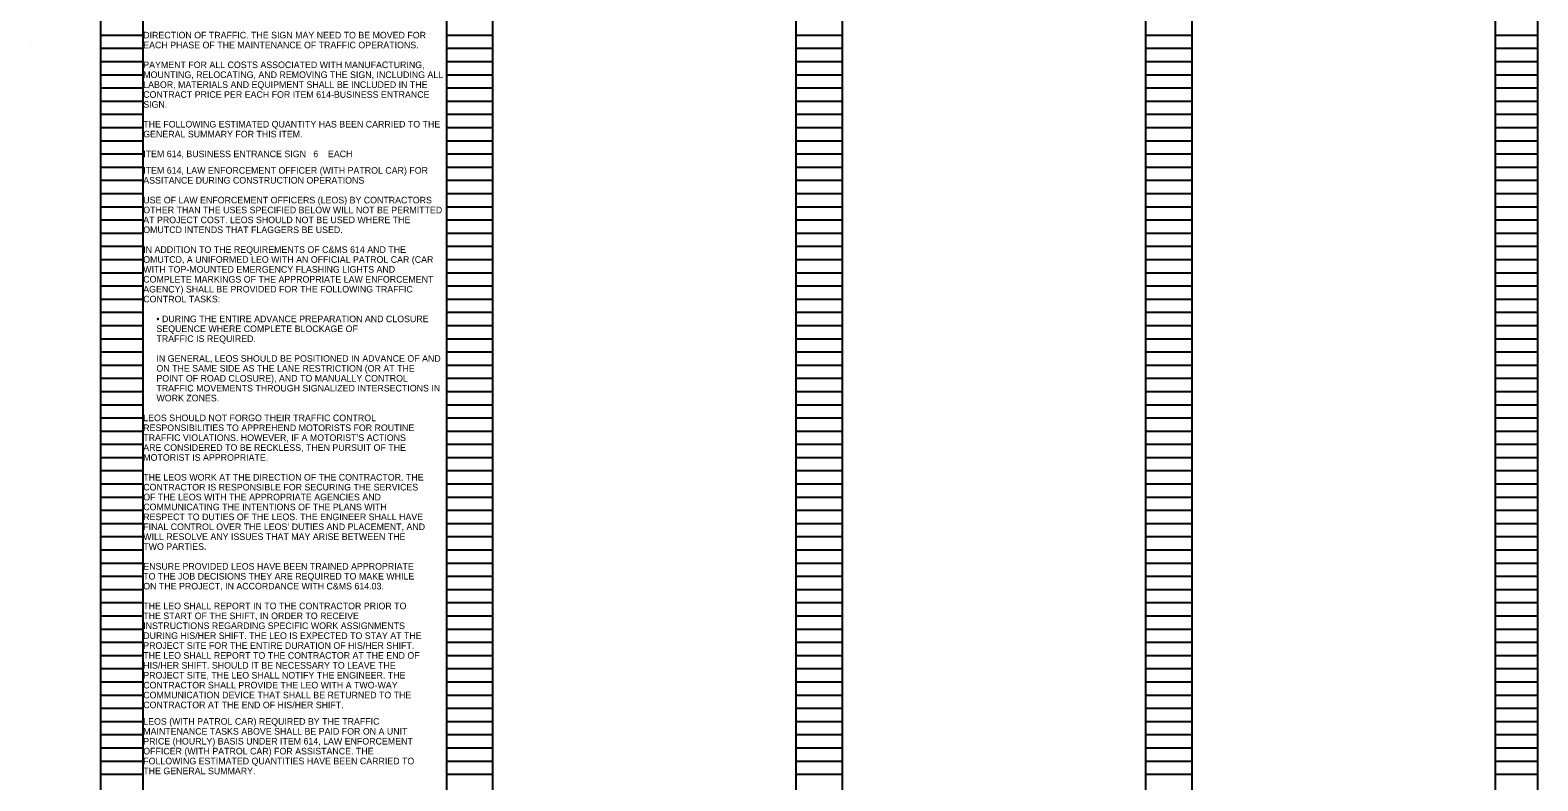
# Model space of a CAD drawing. Extents: x 11124 to 11156, y 1608 to 1730.
# Drawn here: x 11124.4 to 11156.4, y 1653.07 to 1668.99 of the extents above; entities that cross this region are included whole.
import ezdxf

# ---------------------------------------------------------------- set-up
doc = ezdxf.new("R2010")
doc.units = 0
doc.layers.add('SC_Scratch1', color=7, linetype='Continuous')
doc.layers.add('SH_Text', color=7, linetype='Continuous')

msp = doc.modelspace()

# ---------------------------------------------------------------- linework, layer by layer
at = {"layer": 'SC_Scratch1'}
for p, q in [((11125.896, 1649.569), (11125.896, 1669.729)), ((11126.796, 1649.569), (11126.796, 1669.729)), ((11133.236, 1649.569), (11133.236, 1669.729)), ((11134.216, 1649.569), (11134.216, 1669.729)), ((11140.656, 1649.569), (11140.656, 1669.729)), ((11141.636, 1649.569), (11141.636, 1669.729)), ((11148.076, 1649.569), (11148.076, 1669.729)), ((11149.056, 1649.569), (11149.056, 1669.729)), ((11155.496, 1649.569), (11155.496, 1669.729)), ((11156.396, 1649.569), (11156.396, 1669.729)), ((11125.896, 1668.889), (11126.796, 1668.889)), ((11133.236, 1668.889), (11134.216, 1668.889)), ((11140.656, 1668.889), (11141.636, 1668.889)), ((11148.076, 1668.889), (11149.056, 1668.889)), ((11155.496, 1668.889), (11156.396, 1668.889)), ((11124.396, 1668.749), (11124.396, 1668.749)), ((11125.896, 1668.609), (11126.796, 1668.609)), ((11133.236, 1668.609), (11134.216, 1668.609)), ((11140.656, 1668.609), (11141.636, 1668.609)), ((11148.076, 1668.609), (11149.056, 1668.609)), ((11155.496, 1668.609), (11156.396, 1668.609)), ((11125.896, 1668.329), (11126.796, 1668.329)), ((11133.236, 1668.329), (11134.216, 1668.329)), ((11140.656, 1668.329), (11141.636, 1668.329)), ((11148.076, 1668.329), (11149.056, 1668.329)), ((11155.496, 1668.329), (11156.396, 1668.329)), ((11125.896, 1668.049), (11126.796, 1668.049)), ((11133.236, 1668.049), (11134.216, 1668.049)), ((11140.656, 1668.049), (11141.636, 1668.049)), ((11148.076, 1668.049), (11149.056, 1668.049)), ((11155.496, 1668.049), (11156.396, 1668.049)), ((11125.896, 1667.769), (11126.796, 1667.769)), ((11133.236, 1667.769), (11134.216, 1667.769)), ((11140.656, 1667.769), (11141.636, 1667.769)), ((11148.076, 1667.769), (11149.056, 1667.769)), ((11155.496, 1667.769), (11156.396, 1667.769)), ((11125.896, 1667.489), (11126.796, 1667.489)), ((11125.896, 1667.209), (11126.796, 1667.209)), ((11133.236, 1667.489), (11134.216, 1667.489)), ((11133.236, 1667.209), (11134.216, 1667.209)), ((11140.656, 1667.489), (11141.636, 1667.489)), ((11140.656, 1667.209), (11141.636, 1667.209)), ((11148.076, 1667.489), (11149.056, 1667.489)), ((11148.076, 1667.209), (11149.056, 1667.209)), ((11155.496, 1667.489), (11156.396, 1667.489)), ((11155.496, 1667.209), (11156.396, 1667.209)), ((11125.896, 1666.929), (11126.796, 1666.929)), ((11133.236, 1666.929), (11134.216, 1666.929)), ((11140.656, 1666.929), (11141.636, 1666.929)), ((11148.076, 1666.929), (11149.056, 1666.929)), ((11155.496, 1666.929), (11156.396, 1666.929)), ((11125.896, 1666.649), (11126.796, 1666.649)), ((11133.236, 1666.649), (11134.216, 1666.649)), ((11140.656, 1666.649), (11141.636, 1666.649)), ((11148.076, 1666.649), (11149.056, 1666.649)), ((11155.496, 1666.649), (11156.396, 1666.649)), ((11125.896, 1666.369), (11126.796, 1666.369)), ((11133.236, 1666.369), (11134.216, 1666.369)), ((11140.656, 1666.369), (11141.636, 1666.369)), ((11148.076, 1666.369), (11149.056, 1666.369)), ((11155.496, 1666.369), (11156.396, 1666.369)), ((11125.896, 1666.089), (11126.796, 1666.089)), ((11133.236, 1666.089), (11134.216, 1666.089)), ((11140.656, 1666.089), (11141.636, 1666.089)), ((11148.076, 1666.089), (11149.056, 1666.089)), ((11155.496, 1666.089), (11156.396, 1666.089)), ((11125.896, 1665.809), (11126.796, 1665.809)), ((11133.236, 1665.809), (11134.216, 1665.809)), ((11140.656, 1665.809), (11141.636, 1665.809)), ((11148.076, 1665.809), (11149.056, 1665.809)), ((11155.496, 1665.809), (11156.396, 1665.809)), ((11125.896, 1665.529), (11126.796, 1665.529)), ((11133.236, 1665.529), (11134.216, 1665.529)), ((11140.656, 1665.529), (11141.636, 1665.529)), ((11148.076, 1665.529), (11149.056, 1665.529)), ((11155.496, 1665.529), (11156.396, 1665.529)), ((11125.896, 1665.249), (11126.796, 1665.249)), ((11125.896, 1664.969), (11126.796, 1664.969)), ((11133.236, 1665.249), (11134.216, 1665.249)), ((11133.236, 1664.969), (11134.216, 1664.969)), ((11140.656, 1665.249), (11141.636, 1665.249)), ((11140.656, 1664.969), (11141.636, 1664.969)), ((11148.076, 1665.249), (11149.056, 1665.249)), ((11148.076, 1664.969), (11149.056, 1664.969)), ((11155.496, 1665.249), (11156.396, 1665.249)), ((11155.496, 1664.969), (11156.396, 1664.969)), ((11125.896, 1664.689), (11126.796, 1664.689)), ((11133.236, 1664.689), (11134.216, 1664.689)), ((11140.656, 1664.689), (11141.636, 1664.689)), ((11148.076, 1664.689), (11149.056, 1664.689)), ((11155.496, 1664.689), (11156.396, 1664.689)), ((11125.896, 1664.409), (11126.796, 1664.409)), ((11133.236, 1664.409), (11134.216, 1664.409)), ((11140.656, 1664.409), (11141.636, 1664.409)), ((11148.076, 1664.409), (11149.056, 1664.409)), ((11155.496, 1664.409), (11156.396, 1664.409)), ((11125.896, 1664.129), (11126.796, 1664.129)), ((11133.236, 1664.129), (11134.216, 1664.129)), ((11140.656, 1664.129), (11141.636, 1664.129)), ((11148.076, 1664.129), (11149.056, 1664.129)), ((11155.496, 1664.129), (11156.396, 1664.129)), ((11125.896, 1663.849), (11126.796, 1663.849)), ((11133.236, 1663.849), (11134.216, 1663.849)), ((11140.656, 1663.849), (11141.636, 1663.849)), ((11148.076, 1663.849), (11149.056, 1663.849)), ((11155.496, 1663.849), (11156.396, 1663.849)), ((11125.896, 1663.569), (11126.796, 1663.569)), ((11133.236, 1663.569), (11134.216, 1663.569)), ((11140.656, 1663.569), (11141.636, 1663.569)), ((11148.076, 1663.569), (11149.056, 1663.569)), ((11155.496, 1663.569), (11156.396, 1663.569)), ((11125.896, 1663.289), (11126.796, 1663.289)), ((11133.236, 1663.289), (11134.216, 1663.289)), ((11140.656, 1663.289), (11141.636, 1663.289)), ((11148.076, 1663.289), (11149.056, 1663.289)), ((11155.496, 1663.289), (11156.396, 1663.289)), ((11125.896, 1663.009), (11126.796, 1663.009)), ((11125.896, 1662.729), (11126.796, 1662.729)), ((11133.236, 1663.009), (11134.216, 1663.009)), ((11133.236, 1662.729), (11134.216, 1662.729)), ((11140.656, 1663.009), (11141.636, 1663.009)), ((11140.656, 1662.729), (11141.636, 1662.729)), ((11148.076, 1663.009), (11149.056, 1663.009)), ((11148.076, 1662.729), (11149.056, 1662.729)), ((11155.496, 1663.009), (11156.396, 1663.009)), ((11155.496, 1662.729), (11156.396, 1662.729)), ((11125.896, 1662.449), (11126.796, 1662.449)), ((11133.236, 1662.449), (11134.216, 1662.449)), ((11140.656, 1662.449), (11141.636, 1662.449)), ((11148.076, 1662.449), (11149.056, 1662.449)), ((11155.496, 1662.449), (11156.396, 1662.449)), ((11125.896, 1662.169), (11126.796, 1662.169)), ((11133.236, 1662.169), (11134.216, 1662.169)), ((11140.656, 1662.169), (11141.636, 1662.169)), ((11148.076, 1662.169), (11149.056, 1662.169)), ((11155.496, 1662.169), (11156.396, 1662.169)), ((11125.896, 1661.889), (11126.796, 1661.889)), ((11133.236, 1661.889), (11134.216, 1661.889)), ((11140.656, 1661.889), (11141.636, 1661.889)), ((11148.076, 1661.889), (11149.056, 1661.889)), ((11155.496, 1661.889), (11156.396, 1661.889)), ((11125.896, 1661.609), (11126.796, 1661.609)), ((11133.236, 1661.609), (11134.216, 1661.609)), ((11140.656, 1661.609), (11141.636, 1661.609)), ((11148.076, 1661.609), (11149.056, 1661.609)), ((11155.496, 1661.609), (11156.396, 1661.609)), ((11125.896, 1661.329), (11126.796, 1661.329)), ((11133.236, 1661.329), (11134.216, 1661.329)), ((11140.656, 1661.329), (11141.636, 1661.329)), ((11148.076, 1661.329), (11149.056, 1661.329)), ((11155.496, 1661.329), (11156.396, 1661.329)), ((11125.896, 1661.049), (11126.796, 1661.049)), ((11133.236, 1661.049), (11134.216, 1661.049)), ((11140.656, 1661.049), (11141.636, 1661.049)), ((11148.076, 1661.049), (11149.056, 1661.049)), ((11155.496, 1661.049), (11156.396, 1661.049)), ((11125.896, 1660.769), (11126.796, 1660.769)), ((11125.896, 1660.489), (11126.796, 1660.489)), ((11133.236, 1660.769), (11134.216, 1660.769)), ((11133.236, 1660.489), (11134.216, 1660.489)), ((11140.656, 1660.769), (11141.636, 1660.769)), ((11140.656, 1660.489), (11141.636, 1660.489)), ((11148.076, 1660.769), (11149.056, 1660.769)), ((11148.076, 1660.489), (11149.056, 1660.489)), ((11155.496, 1660.769), (11156.396, 1660.769)), ((11155.496, 1660.489), (11156.396, 1660.489)), ((11125.896, 1660.209), (11126.796, 1660.209)), ((11133.236, 1660.209), (11134.216, 1660.209)), ((11140.656, 1660.209), (11141.636, 1660.209)), ((11148.076, 1660.209), (11149.056, 1660.209)), ((11155.496, 1660.209), (11156.396, 1660.209)), ((11125.896, 1659.929), (11126.796, 1659.929)), ((11133.236, 1659.929), (11134.216, 1659.929)), ((11140.656, 1659.929), (11141.636, 1659.929)), ((11148.076, 1659.929), (11149.056, 1659.929)), ((11155.496, 1659.929), (11156.396, 1659.929)), ((11125.896, 1659.649), (11126.796, 1659.649)), ((11133.236, 1659.649), (11134.216, 1659.649)), ((11140.656, 1659.649), (11141.636, 1659.649)), ((11148.076, 1659.649), (11149.056, 1659.649)), ((11155.496, 1659.649), (11156.396, 1659.649)), ((11125.896, 1659.369), (11126.796, 1659.369)), ((11133.236, 1659.369), (11134.216, 1659.369)), ((11140.656, 1659.369), (11141.636, 1659.369)), ((11148.076, 1659.369), (11149.056, 1659.369)), ((11155.496, 1659.369), (11156.396, 1659.369)), ((11125.896, 1659.089), (11126.796, 1659.089)), ((11133.236, 1659.089), (11134.216, 1659.089)), ((11140.656, 1659.089), (11141.636, 1659.089)), ((11148.076, 1659.089), (11149.056, 1659.089)), ((11155.496, 1659.089), (11156.396, 1659.089)), ((11125.896, 1658.809), (11126.796, 1658.809)), ((11133.236, 1658.809), (11134.216, 1658.809)), ((11140.656, 1658.809), (11141.636, 1658.809)), ((11148.076, 1658.809), (11149.056, 1658.809)), ((11155.496, 1658.809), (11156.396, 1658.809)), ((11125.896, 1658.529), (11126.796, 1658.529)), ((11125.896, 1658.249), (11126.796, 1658.249)), ((11133.236, 1658.529), (11134.216, 1658.529)), ((11133.236, 1658.249), (11134.216, 1658.249)), ((11140.656, 1658.529), (11141.636, 1658.529)), ((11140.656, 1658.249), (11141.636, 1658.249)), ((11148.076, 1658.529), (11149.056, 1658.529)), ((11148.076, 1658.249), (11149.056, 1658.249)), ((11155.496, 1658.529), (11156.396, 1658.529)), ((11155.496, 1658.249), (11156.396, 1658.249)), ((11125.896, 1657.969), (11126.796, 1657.969)), ((11133.236, 1657.969), (11134.216, 1657.969)), ((11140.656, 1657.969), (11141.636, 1657.969)), ((11148.076, 1657.969), (11149.056, 1657.969)), ((11155.496, 1657.969), (11156.396, 1657.969)), ((11125.896, 1657.689), (11126.796, 1657.689)), ((11133.236, 1657.689), (11134.216, 1657.689)), ((11140.656, 1657.689), (11141.636, 1657.689)), ((11148.076, 1657.689), (11149.056, 1657.689)), ((11155.496, 1657.689), (11156.396, 1657.689)), ((11125.896, 1657.409), (11126.796, 1657.409)), ((11133.236, 1657.409), (11134.216, 1657.409)), ((11140.656, 1657.409), (11141.636, 1657.409)), ((11148.076, 1657.409), (11149.056, 1657.409)), ((11155.496, 1657.409), (11156.396, 1657.409)), ((11125.896, 1657.129), (11126.796, 1657.129)), ((11133.236, 1657.129), (11134.216, 1657.129)), ((11140.656, 1657.129), (11141.636, 1657.129)), ((11148.076, 1657.129), (11149.056, 1657.129)), ((11155.496, 1657.129), (11156.396, 1657.129)), ((11125.896, 1656.849), (11126.796, 1656.849)), ((11133.236, 1656.849), (11134.216, 1656.849)), ((11140.656, 1656.849), (11141.636, 1656.849)), ((11148.076, 1656.849), (11149.056, 1656.849)), ((11155.496, 1656.849), (11156.396, 1656.849)), ((11125.896, 1656.569), (11126.796, 1656.569)), ((11133.236, 1656.569), (11134.216, 1656.569)), ((11140.656, 1656.569), (11141.636, 1656.569)), ((11148.076, 1656.569), (11149.056, 1656.569)), ((11155.496, 1656.569), (11156.396, 1656.569)), ((11125.896, 1656.289), (11126.796, 1656.289)), ((11125.896, 1656.009), (11126.796, 1656.009)), ((11133.236, 1656.289), (11134.216, 1656.289)), ((11133.236, 1656.009), (11134.216, 1656.009)), ((11140.656, 1656.289), (11141.636, 1656.289)), ((11140.656, 1656.009), (11141.636, 1656.009)), ((11148.076, 1656.289), (11149.056, 1656.289)), ((11148.076, 1656.009), (11149.056, 1656.009)), ((11155.496, 1656.289), (11156.396, 1656.289)), ((11155.496, 1656.009), (11156.396, 1656.009)), ((11125.896, 1655.729), (11126.796, 1655.729)), ((11133.236, 1655.729), (11134.216, 1655.729)), ((11140.656, 1655.729), (11141.636, 1655.729)), ((11148.076, 1655.729), (11149.056, 1655.729)), ((11155.496, 1655.729), (11156.396, 1655.729)), ((11125.896, 1655.449), (11126.796, 1655.449)), ((11133.236, 1655.449), (11134.216, 1655.449)), ((11140.656, 1655.449), (11141.636, 1655.449)), ((11148.076, 1655.449), (11149.056, 1655.449)), ((11155.496, 1655.449), (11156.396, 1655.449)), ((11125.896, 1655.169), (11126.796, 1655.169)), ((11133.236, 1655.169), (11134.216, 1655.169)), ((11140.656, 1655.169), (11141.636, 1655.169)), ((11148.076, 1655.169), (11149.056, 1655.169)), ((11155.496, 1655.169), (11156.396, 1655.169)), ((11125.896, 1654.889), (11126.796, 1654.889)), ((11133.236, 1654.889), (11134.216, 1654.889)), ((11140.656, 1654.889), (11141.636, 1654.889)), ((11148.076, 1654.889), (11149.056, 1654.889)), ((11155.496, 1654.889), (11156.396, 1654.889)), ((11125.896, 1654.609), (11126.796, 1654.609)), ((11133.236, 1654.609), (11134.216, 1654.609)), ((11140.656, 1654.609), (11141.636, 1654.609)), ((11148.076, 1654.609), (11149.056, 1654.609)), ((11155.496, 1654.609), (11156.396, 1654.609)), ((11125.896, 1654.329), (11126.796, 1654.329)), ((11133.236, 1654.329), (11134.216, 1654.329)), ((11140.656, 1654.329), (11141.636, 1654.329)), ((11148.076, 1654.329), (11149.056, 1654.329)), ((11155.496, 1654.329), (11156.396, 1654.329)), ((11125.896, 1654.049), (11126.796, 1654.049)), ((11125.896, 1653.769), (11126.796, 1653.769)), ((11133.236, 1654.049), (11134.216, 1654.049)), ((11133.236, 1653.769), (11134.216, 1653.769)), ((11140.656, 1654.049), (11141.636, 1654.049)), ((11140.656, 1653.769), (11141.636, 1653.769)), ((11148.076, 1654.049), (11149.056, 1654.049)), ((11148.076, 1653.769), (11149.056, 1653.769)), ((11155.496, 1654.049), (11156.396, 1654.049)), ((11155.496, 1653.769), (11156.396, 1653.769)), ((11125.896, 1653.489), (11126.796, 1653.489)), ((11133.236, 1653.489), (11134.216, 1653.489)), ((11140.656, 1653.489), (11141.636, 1653.489)), ((11148.076, 1653.489), (11149.056, 1653.489)), ((11155.496, 1653.489), (11156.396, 1653.489)), ((11125.896, 1653.209), (11126.796, 1653.209)), ((11133.236, 1653.209), (11134.216, 1653.209)), ((11140.656, 1653.209), (11141.636, 1653.209)), ((11148.076, 1653.209), (11149.056, 1653.209)), ((11155.496, 1653.209), (11156.396, 1653.209))]:
    msp.add_line(p, q, dxfattribs=at)

# ---------------------------------------------------------------- texts
at = {"layer": 'SH_Text'}
for s, p in [('DIRECTION OF TRAFFIC. THE SIGN MAY NEED TO BE MOVED FOR ', (11126.796, 1668.819)), ('EACH PHASE OF THE MAINTENANCE OF TRAFFIC OPERATIONS.', (11126.796, 1668.609)), ('PAYMENT FOR ALL COSTS ASSOCIATED WITH MANUFACTURING, ', (11126.796, 1668.189)), ('MOUNTING, RELOCATING, AND REMOVING THE SIGN, INCLUDING ALL ', (11126.796, 1667.979)), ('LABOR, MATERIALS AND EQUIPMENT SHALL BE INCLUDED IN THE ', (11126.796, 1667.769)), ('CONTRACT PRICE PER EACH FOR ITEM 614-BUSINESS ENTRANCE ', (11126.796, 1667.559)), ('SIGN.', (11126.796, 1667.349)), ('THE FOLLOWING ESTIMATED QUANTITY HAS BEEN CARRIED TO THE ', (11126.796, 1666.929)), ('GENERAL SUMMARY FOR THIS ITEM.', (11126.796, 1666.719)), ('ITEM 614, BUSINESS ENTRANCE SIGN   6', (11126.796, 1666.299)), ('EACH', (11130.716, 1666.299)), ('ITEM 614, LAW ENFORCEMENT OFFICER (WITH PATROL CAR) FOR ', (11126.796, 1665.949)), ('ASSITANCE DURING CONSTRUCTION OPERATIONS', (11126.796, 1665.739)), ('USE OF LAW ENFORCEMENT OFFICERS (LEOS) BY CONTRACTORS ', (11126.796, 1665.319)), ('AT PROJECT COST. LEOS SHOULD NOT BE USED WHERE THE ', (11126.796, 1664.899)), ('OTHER THAN THE USES SPECIFIED BELOW WILL NOT BE PERMITTED ', (11126.796, 1665.109)), ('OMUTCD INTENDS THAT FLAGGERS BE USED.', (11126.796, 1664.689)), ('IN ADDITION TO THE REQUIREMENTS OF C&MS 614 AND THE ', (11126.796, 1664.269)), ('OMUTCD, A UNIFORMED LEO WITH AN OFFICIAL PATROL CAR (CAR ', (11126.796, 1664.059)), ('WITH TOP-MOUNTED EMERGENCY FLASHING LIGHTS AND ', (11126.796, 1663.849)), ('COMPLETE MARKINGS OF THE APPROPRIATE LAW ENFORCEMENT ', (11126.796, 1663.639)), ('AGENCY) SHALL BE PROVIDED FOR THE FOLLOWING TRAFFIC ', (11126.796, 1663.429)), ('CONTROL TASKS:', (11126.796, 1663.219)), ('• DURING THE ENTIRE ADVANCE PREPARATION AND CLOSURE ', (11127.076, 1662.799)), ('SEQUENCE WHERE COMPLETE BLOCKAGE OF', (11127.076, 1662.589)), ('TRAFFIC IS REQUIRED.', (11127.076, 1662.379)), ('IN GENERAL, LEOS SHOULD BE POSITIONED IN ADVANCE OF AND ', (11127.076, 1661.959)), ('ON THE SAME SIDE AS THE LANE RESTRICTION (OR AT THE ', (11127.076, 1661.749)), ('TRAFFIC MOVEMENTS THROUGH SIGNALIZED INTERSECTIONS IN ', (11127.076, 1661.329)), ('POINT OF ROAD CLOSURE), AND TO MANUALLY CONTROL ', (11127.076, 1661.539)), ('WORK ZONES.', (11127.076, 1661.119)), ('LEOS SHOULD NOT FORGO THEIR TRAFFIC CONTROL ', (11126.796, 1660.699)), ('RESPONSIBILITIES TO APPREHEND MOTORISTS FOR ROUTINE ', (11126.796, 1660.489)), ('ARE CONSIDERED TO BE RECKLESS, THEN PURSUIT OF THE ', (11126.796, 1660.069)), ('TRAFFIC VIOLATIONS. HOWEVER, IF A MOTORIST’S ACTIONS ', (11126.796, 1660.279)), ('MOTORIST IS APPROPRIATE.', (11126.796, 1659.859)), ('THE LEOS WORK AT THE DIRECTION OF THE CONTRACTOR. THE ', (11126.796, 1659.439)), ('CONTRACTOR IS RESPONSIBLE FOR SECURING THE SERVICES ', (11126.796, 1659.229)), ('OF THE LEOS WITH THE APPROPRIATE AGENCIES AND ', (11126.796, 1659.019)), ('COMMUNICATING THE INTENTIONS OF THE PLANS WITH ', (11126.796, 1658.809)), ('RESPECT TO DUTIES OF THE LEOS. THE ENGINEER SHALL HAVE ', (11126.796, 1658.599)), ('WILL RESOLVE ANY ISSUES THAT MAY ARISE BETWEEN THE ', (11126.796, 1658.179)), ('FINAL CONTROL OVER THE LEOS’ DUTIES AND PLACEMENT, AND ', (11126.796, 1658.389)), ('TWO PARTIES.', (11126.796, 1657.969)), ('ENSURE PROVIDED LEOS HAVE BEEN TRAINED APPROPRIATE ', (11126.796, 1657.549)), ('TO THE JOB DECISIONS THEY ARE REQUIRED TO MAKE WHILE ', (11126.796, 1657.339)), ('ON THE PROJECT, IN ACCORDANCE WITH C&MS 614.03.', (11126.796, 1657.129)), ('THE LEO SHALL REPORT IN TO THE CONTRACTOR PRIOR TO ', (11126.796, 1656.709)), ('THE START OF THE SHIFT, IN ORDER TO RECEIVE ', (11126.796, 1656.499)), ('INSTRUCTIONS REGARDING SPECIFIC WORK ASSIGNMENTS ', (11126.796, 1656.289)), ('DURING HIS/HER SHIFT. THE LEO IS EXPECTED TO STAY AT THE ', (11126.796, 1656.079)), ('PROJECT SITE FOR THE ENTIRE DURATION OF HIS/HER SHIFT. ', (11126.796, 1655.869)), ('THE LEO SHALL REPORT TO THE CONTRACTOR AT THE END OF ', (11126.796, 1655.659)), ('HIS/HER SHIFT. SHOULD IT BE NECESSARY TO LEAVE THE ', (11126.796, 1655.449)), ('PROJECT SITE, THE LEO SHALL NOTIFY THE ENGINEER. THE ', (11126.796, 1655.239)), ('CONTRACTOR SHALL PROVIDE THE LEO WITH A TWO-WAY ', (11126.796, 1655.029)), ('COMMUNICATION DEVICE THAT SHALL BE RETURNED TO THE ', (11126.796, 1654.819)), ('CONTRACTOR AT THE END OF HIS/HER SHIFT.', (11126.796, 1654.609)), ('LEOS (WITH PATROL CAR) REQUIRED BY THE TRAFFIC ', (11126.796, 1654.259)), ('MAINTENANCE TASKS ABOVE SHALL BE PAID FOR ON A UNIT ', (11126.796, 1654.049)), ('OFFICER (WITH PATROL CAR) FOR ASSISTANCE. THE ', (11126.796, 1653.629)), ('PRICE (HOURLY) BASIS UNDER ITEM 614, LAW ENFORCEMENT ', (11126.796, 1653.839)), ('FOLLOWING ESTIMATED QUANTITIES HAVE BEEN CARRIED TO ', (11126.796, 1653.419)), ('THE GENERAL SUMMARY.', (11126.796, 1653.209))]:
    msp.add_text(s, height=0.14, dxfattribs=at).set_placement(p)

doc.saveas('drawing.dxf')
